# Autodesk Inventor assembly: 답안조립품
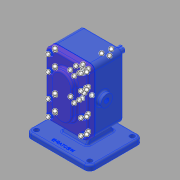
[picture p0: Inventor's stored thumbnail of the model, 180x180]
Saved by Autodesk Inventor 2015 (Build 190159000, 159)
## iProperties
Created: 2020-04
Part Number: 답안조립품
Document SubType Name: Assembly
Designer: CAD02
Author: CAD02
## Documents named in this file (11)
- C:\Users\CAD02\Desktop\700407V1030\답안조립품.iam
- C:\Users\CAD02\Desktop\700407V1030\Ű 6 x 6 x 18.ipt
- C:\Users\CAD02\Desktop\700407V1030\개스킷.ipt
- C:\Users\CAD02\Desktop\700407V1030\메인축.ipt
- C:\Users\CAD02\Desktop\700407V1030\베어링부시.ipt
- C:\Users\CAD02\Desktop\700407V1030\본체.ipt
- C:\Users\CAD02\Desktop\700407V1030\볼트 M5.ipt
- C:\Users\CAD02\Desktop\700407V1030\서브축.ipt
- C:\Users\CAD02\Desktop\700407V1030\스퍼기어.ipt
- C:\Users\CAD02\Desktop\700407V1030\오일 실 16 28 7.ipt
- C:\Users\CAD02\Desktop\700407V1030\커버.ipt
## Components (3 placed, 2 different names)
1. Ű 6 x 6 x 18:1 — 각도:1, 각도:4
2. 개스킷:1
3. Ű 6 x 6 x 18:2 — 각도:2, 각도:3
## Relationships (4: Angle 4)
- 각도:1 [Angle]: Ű 6 x 6 x 18:1
- 각도:2 [Angle]: Ű 6 x 6 x 18:2
- 각도:3 [Angle]: Ű 6 x 6 x 18:2
- 각도:4 [Angle]: Ű 6 x 6 x 18:1
